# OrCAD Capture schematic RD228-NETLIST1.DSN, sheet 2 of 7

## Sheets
2 6: size A3
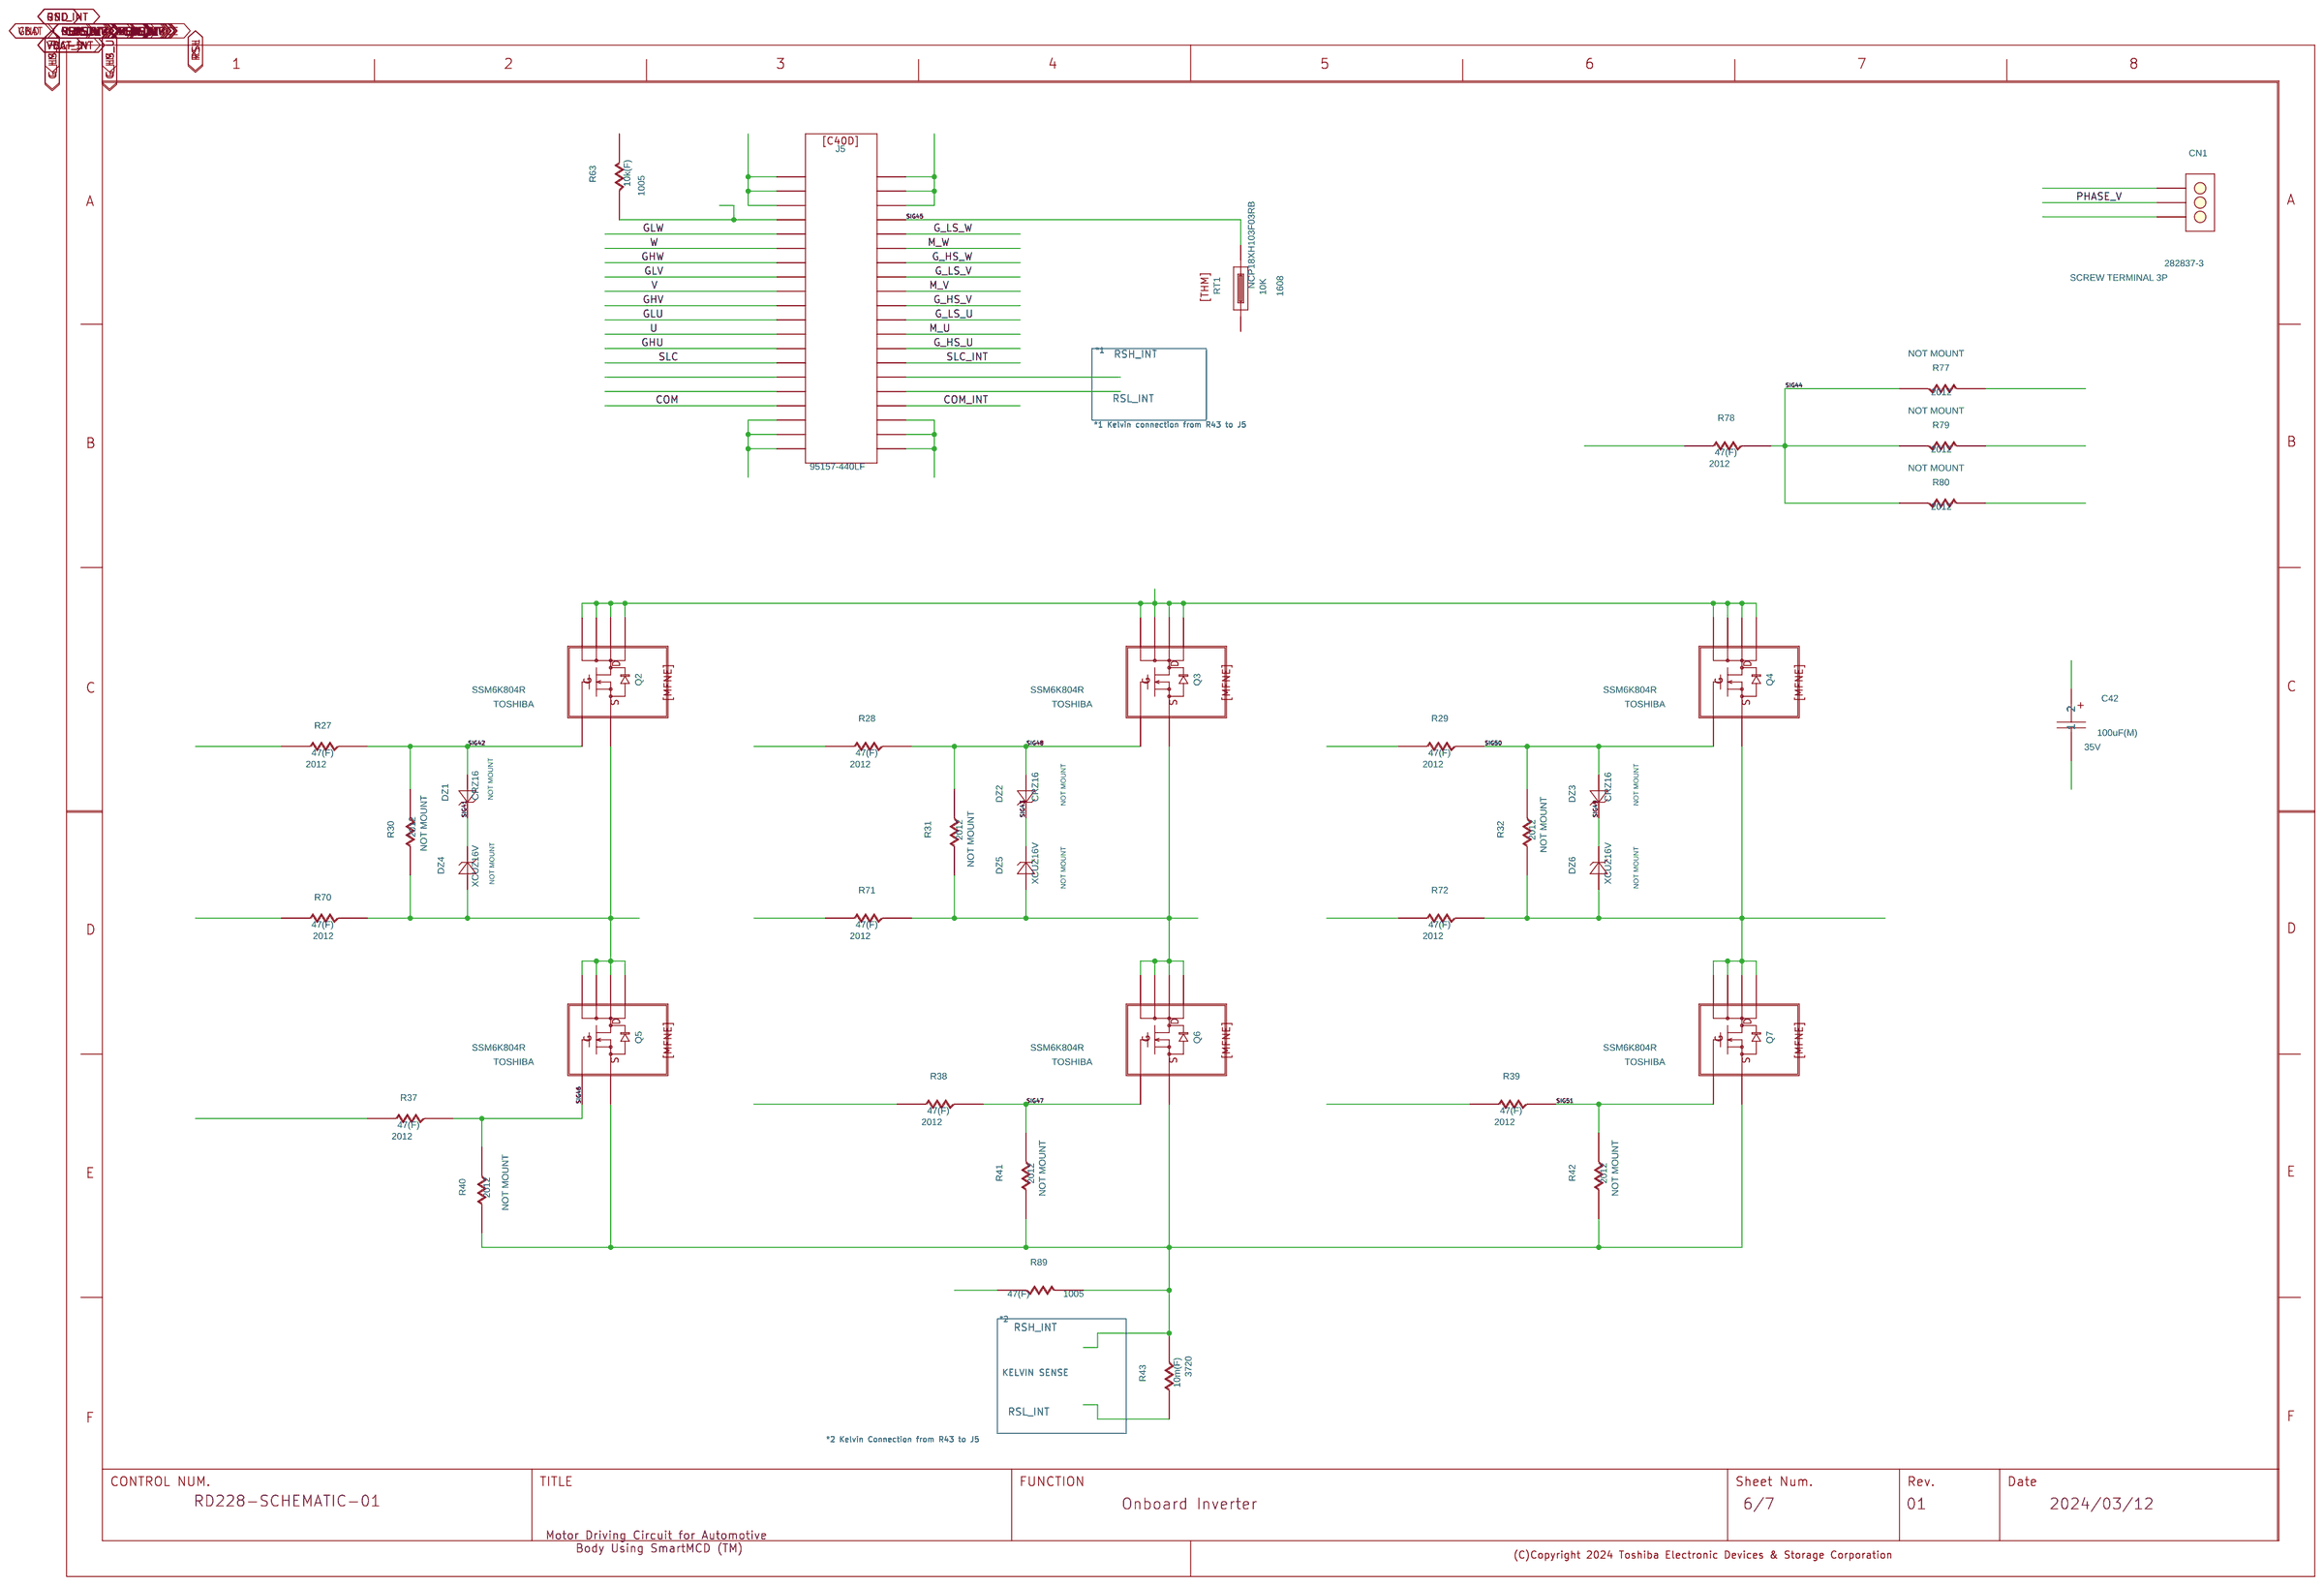
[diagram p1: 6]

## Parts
C42  100ƒÊF  [CAPAE660X550D700DD185L260N]
CN1  SCREW TERMINAL 3P  [SCREW_TERMINAL_3P_5_08]
DZ1  CRZ16  [SFLAT300P360X150X100-2N]
DZ2  CRZ16  [SFLAT300P360X150X100-2N]
DZ3  CRZ16  [SFLAT300P360X150X100-2N]
DZ4  NA  [XCUZ230P125X250X100-2N]
DZ5  NA  [XCUZ230P125X250X100-2N]
DZ6  NA  [XCUZ230P125X250X100-2N]
J5  HM 2x20  [HM254P2x20-SMD]
Q2  NA  [TSOP6F95P220X290X80-6N]
Q3  NA  [TSOP6F95P220X290X80-6N]
Q4  NA  [TSOP6F95P220X290X80-6N]
Q5  NA  [TSOP6F95P220X290X80-6N]
Q6  NA  [TSOP6F95P220X290X80-6N]
Q7  NA  [TSOP6F95P220X290X80-6N]
R27  47  [RESC2013X38N-0805-NOOVERLAY]
R28  47  [RESC2013X38N-0805-NOOVERLAY]
R29  47  [RESC2013X38N-0805-NOOVERLAY]
R30  9.1k  [RESC2013X38N-0805-NOOVERLAY]
R31  9.1k  [RESC2013X38N-0805-NOOVERLAY]
R32  9.1k  [RESC2013X38N-0805-NOOVERLAY]
R37  47  [RESC2013X38N-0805-NOOVERLAY]
R38  47  [RESC2013X38N-0805-NOOVERLAY]
R39  47  [RESC2013X38N-0805-NOOVERLAY]
R40  9.1k  [RESC2013X38N-0805-NOOVERLAY]
R41  9.1k  [RESC2013X38N-0805-NOOVERLAY]
R42  9.1k  [RESC2013X38N-0805-NOOVERLAY]
R43  0.01  [RES1508wide]
R63  10k  [RESC1005X40N-0402-NOOVERLAY]
R70  47  [RESC2013X38N-0805-NOOVERLAY]
R71  47  [RESC2013X38N-0805-NOOVERLAY]
R72  47  [RESC2013X38N-0805-NOOVERLAY]
R77  10k  [RESC2013X38N-0805-NOOVERLAY]
R78  47  [RESC2013X38N-0805-NOOVERLAY]
R79  10k  [RESC2013X38N-0805-NOOVERLAY]
R80  10k  [RESC2013X38N-0805-NOOVERLAY]
R89  47  [RESC1005X40N-0402-NOOVERLAY]
RT1  NA  [RESC1508X55N-0603-NOOVERLAY]
U?#1  WAKU_DEF100

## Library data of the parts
C42 = CP: ASSEMBLY: SMD; BARCODE: 3500000142313; CATEGORY: Capacitors; COMP: Capacitor_Electrolytic_C42; COMPONENTNAME: Capacitor_Electrolytic_C42_Capacitor_Electrolytic_C42; COMPONENTTYPE: 4; DATASHEET URL: http://nichicon-us.com/english/products/pdfs/e-uwt.pdf; FAMILY: ALUMINUM CAPACITOR; ID: 395; INSTANCENAME: INS5635; ITEM_ID: 12367; LAYOUTNAME: Z-29bafe88-5e4d-49ea-814c-92cf843dcf65.cmp15; MANUFACTURER: Nichicon; MANUFACTURER PART NUMBER: UWT1V101MCL1GS; NUMBER DEVICES IN PACKAGE: 1; PACKAGE CASE: Radial, Can - SMD; PART TYPE: Capacitors; PIN NAMES ROTATE: True; PIN NAMES VISIBLE: False; PIN NUMBERS VISIBLE: False; TOLERANCE: }20%; VAL1: 100uF(M); VAL2: 35V; VAL3: UWT1V101MCL1GS; VOLTAGE RATING: 35V
CN1 = SCREW_TERMINAL_3P: ASSEMBLY: TH; BARCODE: 3500000283597; CATEGORY: Connectors, Interconnects; COMP: SCREW_TERMINAL_3P_CN1; COMPONENTNAME: SCREW_TERMINAL_3P_CN1_SCREW_TERMINAL_3P_CN1; COMPONENTTYPE: 4; DATASHEET URL: https://www.te.com/commerce/DocumentDelivery/DDEController?Action; FAMILY: TERMINAL BLOCK; FEATURES: Interlocking (Side); ID: 1109; INSTANCENAME: INS5817; ITEM_ID: 25504; LAYOUTNAME: Z-29bafe88-5e4d-49ea-814c-92cf843dcf65.cmp142; MANUFACTURER: TE Connectivity AMP Connectors; MANUFACTURER PART NUMBER: 282837-3; MOUNTING TYPE: Through Hole; NUMBER DEVICES IN PACKAGE: 1; NUMBER OF LEVELS: 1; NUMBER OF PINS: 3; PART TYPE: Connectors, Electromechanical; PIN NAMES ROTATE: True; PIN NAMES VISIBLE: False; PIN NUMBERS VISIBLE: False; PITCH: 0.200" (5.08mm); POSITIONS PER LEVEL: 3; VAL3: 282837-3
DZ1 = DIODE_ZENER: ASSEMBLY: SMD; BARCODE: 3500000349811; CATEGORY: Diodes - Zener - Single; COMP: Diode_Zener_DZ1; COMPONENTNAME: Diode_Zener_DZ1_Diode_Zener_DZ1; COMPONENTTYPE: 4; DATASHEET URL: https://toshiba.semicon-storage.com/info/docget.jsp?did; FAMILY: DIODE ZENER; ID: 921; INSTANCENAME: INS5575; ITEM_ID: 32142; LAYOUTNAME: Z-29bafe88-5e4d-49ea-814c-92cf843dcf65.cmp37; MANUFACTURER: Toshiba Semiconductor and Storage; MANUFACTURER PART NUMBER: CRZ16(TE85L,Q,M); NOTMOUNT: NOT MOUNT; NUMBER DEVICES IN PACKAGE: 1; PACKAGE CASE: SOD-123F; PART TYPE: Discrete Semiconductors; PIN NAMES ROTATE: True; PIN NAMES VISIBLE: False; PIN NUMBERS VISIBLE: False; POWER MAX: 700 mW; TOLERANCE: }10%; UPDATEDATE: 2024/2/26; UPDATETIME: 11:30:07; UPDATEUSER: w20165dm; VOLTAGE  FORWARD: 1 V @ 200 mA; VOLTAGE  ZENER: 16 V
DZ2 = DIODE_ZENER: ASSEMBLY: SMD; BARCODE: 3500000349811; CATEGORY: Diodes - Zener - Single; COMP: Diode_Zener_DZ2; COMPONENTNAME: Diode_Zener_DZ2_Diode_Zener_DZ2; COMPONENTTYPE: 4; DATASHEET URL: https://toshiba.semicon-storage.com/info/docget.jsp?did; FAMILY: DIODE ZENER; ID: 921; INSTANCENAME: INS5565; ITEM_ID: 32142; LAYOUTNAME: Z-29bafe88-5e4d-49ea-814c-92cf843dcf65.cmp6; MANUFACTURER: Toshiba Semiconductor and Storage; MANUFACTURER PART NUMBER: CRZ16(TE85L,Q,M); NOTMOUNT: NOT MOUNT; NUMBER DEVICES IN PACKAGE: 1; PACKAGE CASE: SOD-123F; PART TYPE: Discrete Semiconductors; PIN NAMES ROTATE: True; PIN NAMES VISIBLE: False; PIN NUMBERS VISIBLE: False; POWER MAX: 700 mW; TOLERANCE: }10%; UPDATEDATE: 2024/2/26; UPDATETIME: 11:30:07; UPDATEUSER: w20165dm; VOLTAGE  FORWARD: 1 V @ 200 mA; VOLTAGE  ZENER: 16 V
DZ3 = DIODE_ZENER: ASSEMBLY: SMD; BARCODE: 3500000349811; CATEGORY: Diodes - Zener - Single; COMP: Diode_Zener_DZ2; COMPONENTNAME: Diode_Zener_DZ2_Diode_Zener_DZ2; COMPONENTTYPE: 4; DATASHEET URL: https://toshiba.semicon-storage.com/info/docget.jsp?did; FAMILY: DIODE ZENER; ID: 921; INSTANCENAME: INS5565; ITEM_ID: 32142; LAYOUTNAME: Z-29bafe88-5e4d-49ea-814c-92cf843dcf65.cmp129; MANUFACTURER: Toshiba Semiconductor and Storage; MANUFACTURER PART NUMBER: CRZ16(TE85L,Q,M); NOTMOUNT: NOT MOUNT; NUMBER DEVICES IN PACKAGE: 1; PACKAGE CASE: SOD-123F; PART TYPE: Discrete Semiconductors; PIN NAMES ROTATE: True; PIN NAMES VISIBLE: False; PIN NUMBERS VISIBLE: False; POWER MAX: 700 mW; TOLERANCE: }10%; UPDATEDATE: 2024/2/26; UPDATETIME: 11:30:07; UPDATEUSER: w20165dm; VOLTAGE  FORWARD: 1 V @ 200 mA; VOLTAGE  ZENER: 16 V
DZ4 = DIODE_ZENER: ASSEMBLY: SMD; BARCODE: 3500000349828; CATEGORY: Diodes - Zener - Single; COMP: Diode_Zener_DZ4; COMPONENTNAME: Diode_Zener_DZ4_Diode_Zener_DZ4; COMPONENTTYPE: 4; FAMILY: DIODE ZENER; ID: 922; INSTANCENAME: INS5605; ITEM_ID: 32143; LAYOUTNAME: Z-29bafe88-5e4d-49ea-814c-92cf843dcf65.cmp13; MANUFACTURER: Toshiba Semiconductor and Storage; MANUFACTURER PART NUMBER: XCUZ16V; NOTMOUNT: NOT MOUNT; NUMBER DEVICES IN PACKAGE: 1; PACKAGE CASE: SOD-123F; PART TYPE: Discrete Semiconductors; PIN NAMES ROTATE: True; PIN NAMES VISIBLE: False; PIN NUMBERS VISIBLE: False; UPDATEDATE: 2024/2/26; UPDATETIME: 11:30:07; UPDATEUSER: w20165dm; VAL1: XCUZ16V; VAL3: XCUZ16V; VOLTAGE  ZENER: 16 V
DZ5 = DIODE_ZENER: ASSEMBLY: SMD; BARCODE: 3500000349828; CATEGORY: Diodes - Zener - Single; COMP: Diode_Zener_DZ5; COMPONENTNAME: Diode_Zener_DZ5_Diode_Zener_DZ5; COMPONENTTYPE: 4; FAMILY: DIODE ZENER; ID: 922; INSTANCENAME: INS5595; ITEM_ID: 32143; LAYOUTNAME: Z-29bafe88-5e4d-49ea-814c-92cf843dcf65.cmp20; MANUFACTURER: Toshiba Semiconductor and Storage; MANUFACTURER PART NUMBER: XCUZ16V; NOTMOUNT: NOT MOUNT; NUMBER DEVICES IN PACKAGE: 1; PACKAGE CASE: SOD-123F; PART TYPE: Discrete Semiconductors; PIN NAMES ROTATE: True; PIN NAMES VISIBLE: False; PIN NUMBERS VISIBLE: False; UPDATEDATE: 2024/2/26; UPDATETIME: 11:30:07; UPDATEUSER: w20165dm; VAL1: XCUZ16V; VAL3: XCUZ16V; VOLTAGE  ZENER: 16 V
DZ6 = DIODE_ZENER: ASSEMBLY: SMD; BARCODE: 3500000349828; CATEGORY: Diodes - Zener - Single; COMP: Diode_Zener_DZ5; COMPONENTNAME: Diode_Zener_DZ5_Diode_Zener_DZ5; COMPONENTTYPE: 4; FAMILY: DIODE ZENER; ID: 922; INSTANCENAME: INS5595; ITEM_ID: 32143; LAYOUTNAME: Z-29bafe88-5e4d-49ea-814c-92cf843dcf65.cmp137; MANUFACTURER: Toshiba Semiconductor and Storage; MANUFACTURER PART NUMBER: XCUZ16V; NOTMOUNT: NOT MOUNT; NUMBER DEVICES IN PACKAGE: 1; PACKAGE CASE: SOD-123F; PART TYPE: Discrete Semiconductors; PIN NAMES ROTATE: True; PIN NAMES VISIBLE: False; PIN NUMBERS VISIBLE: False; UPDATEDATE: 2024/2/26; UPDATETIME: 11:30:07; UPDATEUSER: w20165dm; VAL1: XCUZ16V; VAL3: XCUZ16V; VOLTAGE  ZENER: 16 V
J5 = C40D: ASSEMBLY: SMD; BARCODE: 3500000135131; CATEGORY: Connectors, Interconnects; COMP: HM_2x20_J5; COMPONENTNAME: HM_2x20_J5_HM_2x20_J5; COMPONENTTYPE: 4; CONNECTOR TYPE: Header, Unshrouded; CONTACT FINISH: Tin; CONTACT TYPE: Male Pin; DATASHEET URL: http://portal.fciconnect.com/Comergent//fci/drawing/95157.pdf; FAMILY: HEADER MALE; ID: 329; INSTANCENAME: INS5943; ITEM_ID: 11646; LAYOUTNAME: Z-29bafe88-5e4d-49ea-814c-92cf843dcf65.cmp36; MANUFACTURER: Amphenol FCI; MANUFACTURER PART NUMBER: 95157-440LF; MOUNTING TYPE: Surface Mount; NUMBER DEVICES IN PACKAGE: 1; NUMBER OF POSITIONS: 40; NUMBER OF ROWS: 2; PART TYPE: Connectors, Electromechanical; PIN NAMES ROTATE: True; PIN NAMES VISIBLE: False; PIN NUMBERS VISIBLE: True; PITCH: 0.100" (2.54mm); TERMINATION: Solder; VAL3: 95157-440LF
Q2 = MFNE: ASSEMBLY: SMD; AUTHOR: t5459927; BARCODE: 3500000348838; CATEGORY: Transistors - FETs, MOSFETs - Single; COMP: SSM6K804R_Q5; COMPONENTNAME: SSM6K804R_Q5_SSM6K804R_Q5; COMPONENTTYPE: 4; CURRENT  CONTINUOUS DRAIN: 12A; DATE: 2024/2/16; DRAIN TO SOURCE VOLTAGE: 40V; FAMILY: FET; FET TYPE: N-Channel; ID: 916; INSTANCENAME: INS4477; ITEM_ID: 32044; LAYOUTNAME: Z-29bafe88-5e4d-49ea-814c-92cf843dcf65.cmp121; MANUFACTURER: Toshiba Semiconductor and Storage; MANUFACTURER PART NUMBER: SSM6K804R; NUMBER DEVICES IN PACKAGE: 1; PACKAGE CASE: TSOP6F; PART TYPE: Discrete Semiconductors; PIN NAMES ROTATE: True; PIN NAMES VISIBLE: False; PIN NUMBERS VISIBLE: True; RDS ON MAX: 12mOhm @ 4A, 4.5V; TIME: 16:56:46; UPDATEDATE: 2024/2/16; UPDATETIME: 16:56:46; UPDATEUSER: t5459927; USERCOMPTEXT3: TOSHIBA; VAL1: SSM6K804R; VAL3: SSM6K804R; VGS: -20/+20
Q3 = MFNE: ASSEMBLY: SMD; AUTHOR: t5459927; BARCODE: 3500000348838; CATEGORY: Transistors - FETs, MOSFETs - Single; COMP: SSM6K804R_Q5; COMPONENTNAME: SSM6K804R_Q5_SSM6K804R_Q5; COMPONENTTYPE: 4; CURRENT  CONTINUOUS DRAIN: 12A; DATE: 2024/2/16; DRAIN TO SOURCE VOLTAGE: 40V; FAMILY: FET; FET TYPE: N-Channel; ID: 916; INSTANCENAME: INS4477; ITEM_ID: 32044; LAYOUTNAME: Z-29bafe88-5e4d-49ea-814c-92cf843dcf65.cmp124; MANUFACTURER: Toshiba Semiconductor and Storage; MANUFACTURER PART NUMBER: SSM6K804R; NUMBER DEVICES IN PACKAGE: 1; PACKAGE CASE: TSOP6F; PART TYPE: Discrete Semiconductors; PIN NAMES ROTATE: True; PIN NAMES VISIBLE: False; PIN NUMBERS VISIBLE: True; RDS ON MAX: 12mOhm @ 4A, 4.5V; TIME: 16:56:46; UPDATEDATE: 2024/2/16; UPDATETIME: 16:56:46; UPDATEUSER: t5459927; USERCOMPTEXT3: TOSHIBA; VAL1: SSM6K804R; VAL3: SSM6K804R; VGS: -20/+20
Q4 = MFNE: ASSEMBLY: SMD; AUTHOR: t5459927; BARCODE: 3500000348838; CATEGORY: Transistors - FETs, MOSFETs - Single; COMP: SSM6K804R_Q5; COMPONENTNAME: SSM6K804R_Q5_SSM6K804R_Q5; COMPONENTTYPE: 4; CURRENT  CONTINUOUS DRAIN: 12A; DATE: 2024/2/16; DRAIN TO SOURCE VOLTAGE: 40V; FAMILY: FET; FET TYPE: N-Channel; ID: 916; INSTANCENAME: INS4477; ITEM_ID: 32044; LAYOUTNAME: Z-29bafe88-5e4d-49ea-814c-92cf843dcf65.cmp126; MANUFACTURER: Toshiba Semiconductor and Storage; MANUFACTURER PART NUMBER: SSM6K804R; NUMBER DEVICES IN PACKAGE: 1; PACKAGE CASE: TSOP6F; PART TYPE: Discrete Semiconductors; PIN NAMES ROTATE: True; PIN NAMES VISIBLE: False; PIN NUMBERS VISIBLE: True; RDS ON MAX: 12mOhm @ 4A, 4.5V; TIME: 16:56:46; UPDATEDATE: 2024/2/16; UPDATETIME: 16:56:46; UPDATEUSER: t5459927; USERCOMPTEXT3: TOSHIBA; VAL1: SSM6K804R; VAL3: SSM6K804R; VGS: -20/+20
Q5 = MFNE: ASSEMBLY: SMD; AUTHOR: t5459927; BARCODE: 3500000348838; CATEGORY: Transistors - FETs, MOSFETs - Single; COMP: SSM6K804R_Q5; COMPONENTNAME: SSM6K804R_Q5_SSM6K804R_Q5; COMPONENTTYPE: 4; CURRENT  CONTINUOUS DRAIN: 12A; DATE: 2024/2/16; DRAIN TO SOURCE VOLTAGE: 40V; FAMILY: FET; FET TYPE: N-Channel; ID: 916; INSTANCENAME: INS4477; ITEM_ID: 32044; LAYOUTNAME: Z-29bafe88-5e4d-49ea-814c-92cf843dcf65.cmp120; MANUFACTURER: Toshiba Semiconductor and Storage; MANUFACTURER PART NUMBER: SSM6K804R; NUMBER DEVICES IN PACKAGE: 1; PACKAGE CASE: TSOP6F; PART TYPE: Discrete Semiconductors; PIN NAMES ROTATE: True; PIN NAMES VISIBLE: False; PIN NUMBERS VISIBLE: True; RDS ON MAX: 12mOhm @ 4A, 4.5V; TIME: 16:56:46; UPDATEDATE: 2024/2/16; UPDATETIME: 16:56:46; UPDATEUSER: t5459927; USERCOMPTEXT3: TOSHIBA; VAL1: SSM6K804R; VAL3: SSM6K804R; VGS: -20/+20
Q6 = MFNE: ASSEMBLY: SMD; AUTHOR: t5459927; BARCODE: 3500000348838; CATEGORY: Transistors - FETs, MOSFETs - Single; COMP: SSM6K804R_Q5; COMPONENTNAME: SSM6K804R_Q5_SSM6K804R_Q5; COMPONENTTYPE: 4; CURRENT  CONTINUOUS DRAIN: 12A; DATE: 2024/2/16; DRAIN TO SOURCE VOLTAGE: 40V; FAMILY: FET; FET TYPE: N-Channel; ID: 916; INSTANCENAME: INS4477; ITEM_ID: 32044; LAYOUTNAME: Z-29bafe88-5e4d-49ea-814c-92cf843dcf65.cmp125; MANUFACTURER: Toshiba Semiconductor and Storage; MANUFACTURER PART NUMBER: SSM6K804R; NUMBER DEVICES IN PACKAGE: 1; PACKAGE CASE: TSOP6F; PART TYPE: Discrete Semiconductors; PIN NAMES ROTATE: True; PIN NAMES VISIBLE: False; PIN NUMBERS VISIBLE: True; RDS ON MAX: 12mOhm @ 4A, 4.5V; TIME: 16:56:46; UPDATEDATE: 2024/2/16; UPDATETIME: 16:56:46; UPDATEUSER: t5459927; USERCOMPTEXT3: TOSHIBA; VAL1: SSM6K804R; VAL3: SSM6K804R; VGS: -20/+20
Q7 = MFNE: ASSEMBLY: SMD; AUTHOR: t5459927; BARCODE: 3500000348838; CATEGORY: Transistors - FETs, MOSFETs - Single; COMP: SSM6K804R_Q5; COMPONENTNAME: SSM6K804R_Q5_SSM6K804R_Q5; COMPONENTTYPE: 4; CURRENT  CONTINUOUS DRAIN: 12A; DATE: 2024/2/16; DRAIN TO SOURCE VOLTAGE: 40V; FAMILY: FET; FET TYPE: N-Channel; ID: 916; INSTANCENAME: INS4477; ITEM_ID: 32044; LAYOUTNAME: Z-29bafe88-5e4d-49ea-814c-92cf843dcf65.cmp133; MANUFACTURER: Toshiba Semiconductor and Storage; MANUFACTURER PART NUMBER: SSM6K804R; NUMBER DEVICES IN PACKAGE: 1; PACKAGE CASE: TSOP6F; PART TYPE: Discrete Semiconductors; PIN NAMES ROTATE: True; PIN NAMES VISIBLE: False; PIN NUMBERS VISIBLE: True; RDS ON MAX: 12mOhm @ 4A, 4.5V; TIME: 16:56:46; UPDATEDATE: 2024/2/16; UPDATETIME: 16:56:46; UPDATEUSER: t5459927; USERCOMPTEXT3: TOSHIBA; VAL1: SSM6K804R; VAL3: SSM6K804R; VGS: -20/+20
R27 = R: ASSEMBLY: SMD; AUTHOR: t5459927; BARCODE: 0100000003824; CATEGORY: Resistors; COMP: Resistor_R27; COMPONENTNAME: Resistor_R27_Resistor_R27; COMPONENTTYPE: 4; DATASHEET URL: http://www.yageo.com/NewPortal/yageodocoutput?fileName; DATE: 2024/2/16; FAMILY: RESISTOR; ID: 124; INSTANCENAME: INS5421; ITEM_ID: 648; LAYOUTNAME: Z-29bafe88-5e4d-49ea-814c-92cf843dcf65.cmp23; MANUFACTURER: Yageo; MANUFACTURER PART NUMBER: RC0805FR-0747RL; NUMBER DEVICES IN PACKAGE: 1; PACKAGE CASE: 0805 (2012 Metric); PART TYPE: Resistors; PIN NAMES ROTATE: True; PIN NAMES VISIBLE: False; PIN NUMBERS VISIBLE: False; POWER: 0.125W, 1/8W; SAVECOUNT: 0; SIZECODESMD: 2012; TEMPERATURE COEFFICIENT: }100ppm/C; TIME: 16:56:58; TOLERANCE: }1%; UPDATEDATE: 2024/2/16; UPDATETIME: 16:56:58; UPDATEUSER: t5459927; VAL1: 47(F); VAL2: 0.125W; VAL3: RC0805FR-0747RL
R28 = R: ASSEMBLY: SMD; AUTHOR: t5459927; BARCODE: 0100000003824; CATEGORY: Resistors; COMP: Resistor_R28; COMPONENTNAME: Resistor_R28_Resistor_R28; COMPONENTTYPE: 4; DATASHEET URL: http://www.yageo.com/NewPortal/yageodocoutput?fileName; DATE: 2024/2/16; FAMILY: RESISTOR; ID: 124; INSTANCENAME: INS5391; ITEM_ID: 648; LAYOUTNAME: Z-29bafe88-5e4d-49ea-814c-92cf843dcf65.cmp21; MANUFACTURER: Yageo; MANUFACTURER PART NUMBER: RC0805FR-0747RL; NUMBER DEVICES IN PACKAGE: 1; PACKAGE CASE: 0805 (2012 Metric); PART TYPE: Resistors; PIN NAMES ROTATE: True; PIN NAMES VISIBLE: False; PIN NUMBERS VISIBLE: False; POWER: 0.125W, 1/8W; SAVECOUNT: 0; SIZECODESMD: 2012; TEMPERATURE COEFFICIENT: }100ppm/C; TIME: 16:56:40; TOLERANCE: }1%; UPDATEDATE: 2024/2/16; UPDATETIME: 16:56:40; UPDATEUSER: t5459927; VAL1: 47(F); VAL2: 0.125W; VAL3: RC0805FR-0747RL
R29 = R: ASSEMBLY: SMD; AUTHOR: t5459927; BARCODE: 0100000003824; CATEGORY: Resistors; COMP: Resistor_R28; COMPONENTNAME: Resistor_R28_Resistor_R28; COMPONENTTYPE: 4; DATASHEET URL: http://www.yageo.com/NewPortal/yageodocoutput?fileName; DATE: 2024/2/16; FAMILY: RESISTOR; ID: 124; INSTANCENAME: INS5391; ITEM_ID: 648; LAYOUTNAME: Z-29bafe88-5e4d-49ea-814c-92cf843dcf65.cmp132; MANUFACTURER: Yageo; MANUFACTURER PART NUMBER: RC0805FR-0747RL; NUMBER DEVICES IN PACKAGE: 1; PACKAGE CASE: 0805 (2012 Metric); PART TYPE: Resistors; PIN NAMES ROTATE: True; PIN NAMES VISIBLE: False; PIN NUMBERS VISIBLE: False; POWER: 0.125W, 1/8W; SAVECOUNT: 0; SIZECODESMD: 2012; TEMPERATURE COEFFICIENT: }100ppm/C; TIME: 16:56:40; TOLERANCE: }1%; UPDATEDATE: 2024/2/16; UPDATETIME: 16:56:40; UPDATEUSER: t5459927; VAL1: 47(F); VAL2: 0.125W; VAL3: RC0805FR-0747RL
R30 = R: ASSEMBLY: SMD; AUTHOR: t5459927; CATEGORY: Resistors; COMP: Resistor_R30; COMPONENTNAME: Resistor_R30_Resistor_R30; COMPONENTTYPE: 4; DATE: 2024/2/16; FAMILY: RESISTOR; ID: 124; INSTANCENAME: INS5411; ITEM_ID: 648; LAYOUTNAME: Z-29bafe88-5e4d-49ea-814c-92cf843dcf65.cmp29; MANUFACTURER: Yageo; NOTMOUNT: NOT MOUNT; NUMBER DEVICES IN PACKAGE: 1; PACKAGE CASE: 0805 (2012 Metric); PART TYPE: Resistors; PIN NAMES ROTATE: True; PIN NAMES VISIBLE: False; PIN NUMBERS VISIBLE: False; POWER: 0.125W, 1/8W; SAVECOUNT: 0; SIZECODESMD: 2012; TEMPERATURE COEFFICIENT: }100ppm/C; TIME: 16:56:45; TOLERANCE: }1%; UPDATEDATE: 2024/2/16; UPDATETIME: 16:56:45; UPDATEUSER: t5459927
R31 = R: ASSEMBLY: SMD; AUTHOR: t5459927; CATEGORY: Resistors; COMP: Resistor_R31; COMPONENTNAME: Resistor_R31_Resistor_R31; COMPONENTTYPE: 4; DATE: 2024/2/16; FAMILY: RESISTOR; ID: 124; INSTANCENAME: INS5381; ITEM_ID: 648; LAYOUTNAME: Z-29bafe88-5e4d-49ea-814c-92cf843dcf65.cmp27; MANUFACTURER: Yageo; NOTMOUNT: NOT MOUNT; NUMBER DEVICES IN PACKAGE: 1; PACKAGE CASE: 0805 (2012 Metric); PART TYPE: Resistors; PIN NAMES ROTATE: True; PIN NAMES VISIBLE: False; PIN NUMBERS VISIBLE: False; POWER: 0.125W, 1/8W; SAVECOUNT: 0; SIZECODESMD: 2012; TEMPERATURE COEFFICIENT: }100ppm/C; TIME: 16:56:50; TOLERANCE: }1%; UPDATEDATE: 2024/2/16; UPDATETIME: 16:56:50; UPDATEUSER: t5459927
R32 = R: ASSEMBLY: SMD; AUTHOR: t5459927; CATEGORY: Resistors; COMP: Resistor_R31; COMPONENTNAME: Resistor_R31_Resistor_R31; COMPONENTTYPE: 4; DATE: 2024/2/16; FAMILY: RESISTOR; ID: 124; INSTANCENAME: INS5381; ITEM_ID: 648; LAYOUTNAME: Z-29bafe88-5e4d-49ea-814c-92cf843dcf65.cmp128; MANUFACTURER: Yageo; NOTMOUNT: NOT MOUNT; NUMBER DEVICES IN PACKAGE: 1; PACKAGE CASE: 0805 (2012 Metric); PART TYPE: Resistors; PIN NAMES ROTATE: True; PIN NAMES VISIBLE: False; PIN NUMBERS VISIBLE: False; POWER: 0.125W, 1/8W; SAVECOUNT: 0; SIZECODESMD: 2012; TEMPERATURE COEFFICIENT: }100ppm/C; TIME: 16:56:50; TOLERANCE: }1%; UPDATEDATE: 2024/2/16; UPDATETIME: 16:56:50; UPDATEUSER: t5459927
R37 = R: ASSEMBLY: SMD; AUTHOR: t5459927; BARCODE: 0100000003824; CATEGORY: Resistors; COMP: Resistor_R37; COMPONENTNAME: Resistor_R37_Resistor_R37; COMPONENTTYPE: 4; DATASHEET URL: http://www.yageo.com/NewPortal/yageodocoutput?fileName; DATE: 2024/2/16; FAMILY: RESISTOR; ID: 124; INSTANCENAME: INS5341; ITEM_ID: 648; LAYOUTNAME: Z-29bafe88-5e4d-49ea-814c-92cf843dcf65.cmp24; MANUFACTURER: Yageo; MANUFACTURER PART NUMBER: RC0805FR-0747RL; NUMBER DEVICES IN PACKAGE: 1; PACKAGE CASE: 0805 (2012 Metric); PART TYPE: Resistors; PIN NAMES ROTATE: True; PIN NAMES VISIBLE: False; PIN NUMBERS VISIBLE: False; POWER: 0.125W, 1/8W; SAVECOUNT: 0; SIZECODESMD: 2012; TEMPERATURE COEFFICIENT: }100ppm/C; TIME: 16:56:42; TOLERANCE: }1%; UPDATEDATE: 2024/2/16; UPDATETIME: 16:56:42; UPDATEUSER: t5459927; VAL1: 47(F); VAL2: 0.125W; VAL3: RC0805FR-0747RL
R38 = R: ASSEMBLY: SMD; AUTHOR: t5459927; BARCODE: 0100000003824; CATEGORY: Resistors; COMP: Resistor_R38; COMPONENTNAME: Resistor_R38_Resistor_R38; COMPONENTTYPE: 4; DATASHEET URL: http://www.yageo.com/NewPortal/yageodocoutput?fileName; DATE: 2024/2/16; FAMILY: RESISTOR; ID: 124; INSTANCENAME: INS5321; ITEM_ID: 648; LAYOUTNAME: Z-29bafe88-5e4d-49ea-814c-92cf843dcf65.cmp11; MANUFACTURER: Yageo; MANUFACTURER PART NUMBER: RC0805FR-0747RL; NUMBER DEVICES IN PACKAGE: 1; PACKAGE CASE: 0805 (2012 Metric); PART TYPE: Resistors; PIN NAMES ROTATE: True; PIN NAMES VISIBLE: False; PIN NUMBERS VISIBLE: False; POWER: 0.125W, 1/8W; SAVECOUNT: 0; SIZECODESMD: 2012; TEMPERATURE COEFFICIENT: }100ppm/C; TIME: 16:56:37; TOLERANCE: }1%; UPDATEDATE: 2024/2/16; UPDATETIME: 16:56:37; UPDATEUSER: t5459927; VAL1: 47(F); VAL2: 0.125W; VAL3: RC0805FR-0747RL
R39 = R: ASSEMBLY: SMD; AUTHOR: t5459927; BARCODE: 0100000003824; CATEGORY: Resistors; COMP: Resistor_R38; COMPONENTNAME: Resistor_R38_Resistor_R38; COMPONENTTYPE: 4; DATASHEET URL: http://www.yageo.com/NewPortal/yageodocoutput?fileName; DATE: 2024/2/16; FAMILY: RESISTOR; ID: 124; INSTANCENAME: INS5321; ITEM_ID: 648; LAYOUTNAME: Z-29bafe88-5e4d-49ea-814c-92cf843dcf65.cmp131; MANUFACTURER: Yageo; MANUFACTURER PART NUMBER: RC0805FR-0747RL; NUMBER DEVICES IN PACKAGE: 1; PACKAGE CASE: 0805 (2012 Metric); PART TYPE: Resistors; PIN NAMES ROTATE: True; PIN NAMES VISIBLE: False; PIN NUMBERS VISIBLE: False; POWER: 0.125W, 1/8W; SAVECOUNT: 0; SIZECODESMD: 2012; TEMPERATURE COEFFICIENT: }100ppm/C; TIME: 16:56:37; TOLERANCE: }1%; UPDATEDATE: 2024/2/16; UPDATETIME: 16:56:37; UPDATEUSER: t5459927; VAL1: 47(F); VAL2: 0.125W; VAL3: RC0805FR-0747RL
R40 = R: ASSEMBLY: SMD; AUTHOR: t5459927; CATEGORY: Resistors; COMP: Resistor_R40; COMPONENTNAME: Resistor_R40_Resistor_R40; COMPONENTTYPE: 4; DATE: 2024/2/16; FAMILY: RESISTOR; ID: 124; INSTANCENAME: INS5331; ITEM_ID: 648; LAYOUTNAME: Z-29bafe88-5e4d-49ea-814c-92cf843dcf65.cmp19; MANUFACTURER: Yageo; NOTMOUNT: NOT MOUNT; NUMBER DEVICES IN PACKAGE: 1; PACKAGE CASE: 0805 (2012 Metric); PART TYPE: Resistors; PIN NAMES ROTATE: True; PIN NAMES VISIBLE: False; PIN NUMBERS VISIBLE: False; POWER: 0.125W, 1/8W; SAVECOUNT: 0; SIZECODESMD: 2012; TEMPERATURE COEFFICIENT: }100ppm/C; TIME: 16:56:52; TOLERANCE: }1%; UPDATEDATE: 2024/2/16; UPDATETIME: 16:56:52; UPDATEUSER: t5459927
R41 = R: ASSEMBLY: SMD; AUTHOR: t5459927; CATEGORY: Resistors; COMP: Resistor_R41; COMPONENTNAME: Resistor_R41_Resistor_R41; COMPONENTTYPE: 4; DATE: 2024/2/16; FAMILY: RESISTOR; ID: 124; INSTANCENAME: INS5311; ITEM_ID: 648; LAYOUTNAME: Z-29bafe88-5e4d-49ea-814c-92cf843dcf65.cmp22; MANUFACTURER: Yageo; NOTMOUNT: NOT MOUNT; NUMBER DEVICES IN PACKAGE: 1; PACKAGE CASE: 0805 (2012 Metric); PART TYPE: Resistors; PIN NAMES ROTATE: True; PIN NAMES VISIBLE: False; PIN NUMBERS VISIBLE: False; POWER: 0.125W, 1/8W; SAVECOUNT: 0; SIZECODESMD: 2012; TEMPERATURE COEFFICIENT: }100ppm/C; TIME: 16:56:48; TOLERANCE: }1%; UPDATEDATE: 2024/2/16; UPDATETIME: 16:56:48; UPDATEUSER: t5459927
R42 = R: ASSEMBLY: SMD; AUTHOR: t5459927; CATEGORY: Resistors; COMP: Resistor_R41; COMPONENTNAME: Resistor_R41_Resistor_R41; COMPONENTTYPE: 4; DATE: 2024/2/16; FAMILY: RESISTOR; ID: 124; INSTANCENAME: INS5311; ITEM_ID: 648; LAYOUTNAME: Z-29bafe88-5e4d-49ea-814c-92cf843dcf65.cmp135; MANUFACTURER: Yageo; NOTMOUNT: NOT MOUNT; NUMBER DEVICES IN PACKAGE: 1; PACKAGE CASE: 0805 (2012 Metric); PART TYPE: Resistors; PIN NAMES ROTATE: True; PIN NAMES VISIBLE: False; PIN NUMBERS VISIBLE: False; POWER: 0.125W, 1/8W; SAVECOUNT: 0; SIZECODESMD: 2012; TEMPERATURE COEFFICIENT: }100ppm/C; TIME: 16:56:48; TOLERANCE: }1%; UPDATEDATE: 2024/2/16; UPDATETIME: 16:56:48; UPDATEUSER: t5459927
R43 = R: ASSEMBLY: SMD; AUTHOR: t5459927; BARCODE: 3500000169150; CATEGORY: Resistors; COMP: Resistor_R43; COMPONENTNAME: Resistor_R43_Resistor_R43; COMPONENTTYPE: 4; DATASHEET URL: http://www.susumu.co.jp/common/pdf/n_catalog_partition07_en.pdf; DATE: 2024/2/16; FAMILY: RESISTOR; ID: 892; INSTANCENAME: INS6213; ITEM_ID: 15050; LAYOUTNAME: Z-29bafe88-5e4d-49ea-814c-92cf843dcf65.cmp5; MANUFACTURER: Susumu; MANUFACTURER PART NUMBER: RL3720WT-R010-F; NUMBER DEVICES IN PACKAGE: 1; PACKAGE CASE: Wide 1508 (3720 Metric), 0815; PART TYPE: Resistors; PIN NAMES ROTATE: True; PIN NAMES VISIBLE: False; PIN NUMBERS VISIBLE: False; POWER: 1W; SAVECOUNT: 0; SIZECODESMD: 3720; TEMPERATURE COEFFICIENT: 0/ +350ppm/C; TIME: 16:56:49; TOLERANCE: }1%; UPDATEDATE: 2024/2/16; UPDATETIME: 16:56:49; UPDATEUSER: t5459927; VAL1: 10m(F); VAL2: 1W; VAL3: RL3720WT-R010-F
R63 = R: ASSEMBLY: SMD; AUTHOR: t5459927; BARCODE: 2911010036805; CATEGORY: Resistors; COMP: Resistor_R63; COMPONENTNAME: Resistor_R63_Resistor_R63; COMPONENTTYPE: 4; DATASHEET URL: http://www.yageo.com/NewPortal/yageodocoutput?fileName; DATE: 2024/2/16; FAMILY: RESISTOR; ID: 68; INSTANCENAME: INS5155; ITEM_ID: 4341; LAYOUTNAME: Z-29bafe88-5e4d-49ea-814c-92cf843dcf65.cmp31; MANUFACTURER: Yageo; MANUFACTURER PART NUMBER: RC0402FR-0710KL; NUMBER DEVICES IN PACKAGE: 1; PACKAGE CASE: 0402 (1005 Metric); PART TYPE: Resistors; PIN NAMES ROTATE: True; PIN NAMES VISIBLE: False; PIN NUMBERS VISIBLE: False; POWER: 0.063W, 1/16W; RECOMMENDED RATING: Platinum; SAVECOUNT: 0; SIZECODESMD: 1005; TEMPERATURE COEFFICIENT: }100ppm/C; TIME: 16:56:42; TOLERANCE: }1%; UPDATEDATE: 2024/2/16; UPDATETIME: 16:56:42; UPDATEUSER: t5459927; VAL1: 10k(F); VAL2: 63mW; VAL3: RC0402FR-0710KL
R70 = R: ASSEMBLY: SMD; AUTHOR: t5459927; BARCODE: 0100000003824; CATEGORY: Resistors; COMP: Resistor_R70; COMPONENTNAME: Resistor_R70_Resistor_R70; COMPONENTTYPE: 4; DATASHEET URL: http://www.yageo.com/NewPortal/yageodocoutput?fileName; DATE: 2024/2/16; FAMILY: RESISTOR; ID: 124; INSTANCENAME: INS5431; ITEM_ID: 648; LAYOUTNAME: Z-29bafe88-5e4d-49ea-814c-92cf843dcf65.cmp10; MANUFACTURER: Yageo; MANUFACTURER PART NUMBER: RC0805FR-0747RL; NUMBER DEVICES IN PACKAGE: 1; PACKAGE CASE: 0805 (2012 Metric); PART TYPE: Resistors; PIN NAMES ROTATE: True; PIN NAMES VISIBLE: False; PIN NUMBERS VISIBLE: False; POWER: 0.125W, 1/8W; SAVECOUNT: 0; SIZECODESMD: 2012; TEMPERATURE COEFFICIENT: }100ppm/C; TIME: 16:56:49; TOLERANCE: }1%; UPDATEDATE: 2024/2/16; UPDATETIME: 16:56:49; UPDATEUSER: t5459927; VAL1: 47(F); VAL2: 0.125W; VAL3: RC0805FR-0747RL
R71 = R: ASSEMBLY: SMD; AUTHOR: t5459927; BARCODE: 0100000003824; CATEGORY: Resistors; COMP: Resistor_R71; COMPONENTNAME: Resistor_R71_Resistor_R71; COMPONENTTYPE: 4; DATASHEET URL: http://www.yageo.com/NewPortal/yageodocoutput?fileName; DATE: 2024/2/16; FAMILY: RESISTOR; ID: 124; INSTANCENAME: INS5401; ITEM_ID: 648; LAYOUTNAME: Z-29bafe88-5e4d-49ea-814c-92cf843dcf65.cmp33; MANUFACTURER: Yageo; MANUFACTURER PART NUMBER: RC0805FR-0747RL; NUMBER DEVICES IN PACKAGE: 1; PACKAGE CASE: 0805 (2012 Metric); PART TYPE: Resistors; PIN NAMES ROTATE: True; PIN NAMES VISIBLE: False; PIN NUMBERS VISIBLE: False; POWER: 0.125W, 1/8W; SAVECOUNT: 0; SIZECODESMD: 2012; TEMPERATURE COEFFICIENT: }100ppm/C; TIME: 16:56:54; TOLERANCE: }1%; UPDATEDATE: 2024/2/16; UPDATETIME: 16:56:54; UPDATEUSER: t5459927; VAL1: 47(F); VAL2: 0.125W; VAL3: RC0805FR-0747RL
R72 = R: ASSEMBLY: SMD; AUTHOR: t5459927; BARCODE: 0100000003824; CATEGORY: Resistors; COMP: Resistor_R71; COMPONENTNAME: Resistor_R71_Resistor_R71; COMPONENTTYPE: 4; DATASHEET URL: http://www.yageo.com/NewPortal/yageodocoutput?fileName; DATE: 2024/2/16; FAMILY: RESISTOR; ID: 124; INSTANCENAME: INS5401; ITEM_ID: 648; LAYOUTNAME: Z-29bafe88-5e4d-49ea-814c-92cf843dcf65.cmp136; MANUFACTURER: Yageo; MANUFACTURER PART NUMBER: RC0805FR-0747RL; NUMBER DEVICES IN PACKAGE: 1; PACKAGE CASE: 0805 (2012 Metric); PART TYPE: Resistors; PIN NAMES ROTATE: True; PIN NAMES VISIBLE: False; PIN NUMBERS VISIBLE: False; POWER: 0.125W, 1/8W; SAVECOUNT: 0; SIZECODESMD: 2012; TEMPERATURE COEFFICIENT: }100ppm/C; TIME: 16:56:54; TOLERANCE: }1%; UPDATEDATE: 2024/2/16; UPDATETIME: 16:56:54; UPDATEUSER: t5459927; VAL1: 47(F); VAL2: 0.125W; VAL3: RC0805FR-0747RL
R77 = R: ASSEMBLY: SMD; AUTHOR: t5459927; BARCODE: 0100000001974; CATEGORY: Resistors; COMP: Resistor_R77; COMPONENTNAME: Resistor_R77_Resistor_R77; COMPONENTTYPE: 4; DATASHEET URL: http://www.yageo.com/NewPortal/yageodocoutput?fileName; DATE: 2024/2/16; FAMILY: RESISTOR; ID: 228; INSTANCENAME: INS6403; ITEM_ID: 462; MANUFACTURER: Yageo; MANUFACTURER PART NUMBER: RC0805FR-0710KL; NOTMOUNT: NOT MOUNT; NUMBER DEVICES IN PACKAGE: 1; PACKAGE CASE: 0805 (2012 Metric); PART TYPE: Resistors; PIN NAMES ROTATE: True; PIN NAMES VISIBLE: False; PIN NUMBERS VISIBLE: False; POWER: 0.125W, 1/8W; RECOMMENDED RATING: Platinum; SAVECOUNT: 0; SIZECODESMD: 2012; TEMPERATURE COEFFICIENT: }100ppm/C; TIME: 16:56:53; TOLERANCE: }1%; UPDATEDATE: 2024/2/16; UPDATETIME: 16:56:53; UPDATEUSER: t5459927
R78 = R: ASSEMBLY: SMD; AUTHOR: t5459927; BARCODE: 0100000003824; CATEGORY: Resistors; COMP: Resistor_R78; COMPONENTNAME: Resistor_R78_Resistor_R78; COMPONENTTYPE: 4; DATASHEET URL: http://www.yageo.com/NewPortal/yageodocoutput?fileName; DATE: 2024/2/16; FAMILY: RESISTOR; ID: 124; INSTANCENAME: INS5625; ITEM_ID: 648; LAYOUTNAME: Z-29bafe88-5e4d-49ea-814c-92cf843dcf65.cmp34; MANUFACTURER: Yageo; MANUFACTURER PART NUMBER: RC0805FR-0747RL; NUMBER DEVICES IN PACKAGE: 1; PACKAGE CASE: 0805 (2012 Metric); PART TYPE: Resistors; PIN NAMES ROTATE: True; PIN NAMES VISIBLE: False; PIN NUMBERS VISIBLE: False; POWER: 0.125W, 1/8W; SAVECOUNT: 0; SIZECODESMD: 2012; TEMPERATURE COEFFICIENT: }100ppm/C; TIME: 16:56:58; TOLERANCE: }1%; UPDATEDATE: 2024/2/16; UPDATETIME: 16:56:58; UPDATEUSER: t5459927; VAL1: 47(F); VAL2: 0.125W; VAL3: RC0805FR-0747RL
R79 = R: ASSEMBLY: SMD; AUTHOR: t5459927; BARCODE: 0100000001974; CATEGORY: Resistors; COMP: Resistor_R79; COMPONENTNAME: Resistor_R79_Resistor_R79; COMPONENTTYPE: 4; DATASHEET URL: http://www.yageo.com/NewPortal/yageodocoutput?fileName; DATE: 2024/2/16; FAMILY: RESISTOR; ID: 228; INSTANCENAME: INS6393; ITEM_ID: 462; MANUFACTURER: Yageo; MANUFACTURER PART NUMBER: RC0805FR-0710KL; NOTMOUNT: NOT MOUNT; NUMBER DEVICES IN PACKAGE: 1; PACKAGE CASE: 0805 (2012 Metric); PART TYPE: Resistors; PIN NAMES ROTATE: True; PIN NAMES VISIBLE: False; PIN NUMBERS VISIBLE: False; POWER: 0.125W, 1/8W; RECOMMENDED RATING: Platinum; SAVECOUNT: 0; SIZECODESMD: 2012; TEMPERATURE COEFFICIENT: }100ppm/C; TIME: 16:56:38; TOLERANCE: }1%; UPDATEDATE: 2024/2/16; UPDATETIME: 16:56:38; UPDATEUSER: t5459927
R80 = R: ASSEMBLY: SMD; AUTHOR: t5459927; BARCODE: 0100000001974; CATEGORY: Resistors; COMP: Resistor_R80; COMPONENTNAME: Resistor_R80_Resistor_R80; COMPONENTTYPE: 4; DATASHEET URL: http://www.yageo.com/NewPortal/yageodocoutput?fileName; DATE: 2024/2/16; FAMILY: RESISTOR; ID: 228; INSTANCENAME: INS6383; ITEM_ID: 462; MANUFACTURER: Yageo; MANUFACTURER PART NUMBER: RC0805FR-0710KL; NOTMOUNT: NOT MOUNT; NUMBER DEVICES IN PACKAGE: 1; PACKAGE CASE: 0805 (2012 Metric); PART TYPE: Resistors; PIN NAMES ROTATE: True; PIN NAMES VISIBLE: False; PIN NUMBERS VISIBLE: False; POWER: 0.125W, 1/8W; RECOMMENDED RATING: Platinum; SAVECOUNT: 0; SIZECODESMD: 2012; TEMPERATURE COEFFICIENT: }100ppm/C; TIME: 16:56:48; TOLERANCE: }1%; UPDATEDATE: 2024/2/16; UPDATETIME: 16:56:48; UPDATEUSER: t5459927
R89 = R: ASSEMBLY: SMD; AUTHOR: t5459927; BARCODE: 2911010041359; CATEGORY: Resistors; COMP: Resistor_R89; COMPONENTNAME: Resistor_R89_Resistor_R89; COMPONENTTYPE: 4; DATASHEET URL: http://www.yageo.com/NewPortal/yageodocoutput?fileName; DATE: 2024/2/16; FAMILY: RESISTOR; ID: 51; INSTANCENAME: INS6367; ITEM_ID: 4815; MANUFACTURER: Yageo; MANUFACTURER PART NUMBER: RC0402FR-0747RL; NUMBER DEVICES IN PACKAGE: 1; PACKAGE CASE: 0402 (1005 Metric); PART TYPE: Resistors; PIN NAMES ROTATE: True; PIN NAMES VISIBLE: False; PIN NUMBERS VISIBLE: False; POWER: 0.063W, 1/16W; SAVECOUNT: 0; SIZECODESMD: 1005; TEMPERATURE COEFFICIENT: }100ppm/C; TIME: 16:56:49; TOLERANCE: }1%; UPDATEDATE: 2024/2/16; UPDATETIME: 16:56:49; UPDATEUSER: t5459927; VAL1: 47(F); VAL2: 63mW; VAL3: RC0402FR-0747RL
RT1 = THM: ASSEMBLY: SMD; BARCODE: 0100000108543; CATEGORY: Sensors, Transducers; COMP: Resistor_NTC_RT1; COMPONENTNAME: Resistor_NTC_RT1_Resistor_NTC_RT1; COMPONENTTYPE: 4; DATASHEET URL: http://www.murata.com/~/media/webrenewal/support/library/catalog/products/thermistor/ntc/r44e.ashx; FAMILY: THERMISTOR NTC; ID: 388; INSTANCENAME: INS5165; ITEM_ID: 9968; MANUFACTURER: Murata Electronics North America; MANUFACTURER PART NUMBER: NCP18XH103F03RB; NUMBER DEVICES IN PACKAGE: 1; PACKAGE CASE: 0603 (1608 Metric); PART TYPE: Resistors; PIN NAMES ROTATE: True; PIN NAMES VISIBLE: False; PIN NUMBERS VISIBLE: False; RESISTANCE IN OHMS 25C: 10k; RESISTANCE TOLERANCE: }1%; SIZECODESMD: 1608; VAL1: 10K; VAL3: NCP18XH103F03RB
U?#1 = WAKU_DEF100: AUTHOR: w20165dm; COMPONENTTYPE: 2; DATE: 2024/03/12; DRAWINGNUMBER: RD228-SCHEMATIC-01; FUNCTION: Onboard Inverter; LAYOUTNAME: Z-29bafe88-5e4d-49ea-814c-92cf843dcf65.cmp51; REVISION: 01; SAVEAREA0: 185750,-43960,448537,75779; SAVECOUNT: 9; SHEETNUMBER: 6/7; SHTSAVECOUNT: 57; TIME: 13:12:26; TITLE: Motor Driving Circuit for Automotive / Body Using SmartMCD (TM); UPDATEDATE: 2024/03/26; UPDATETIME: 12:24:26

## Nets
GND: C42.2(1) J5.35 J5.37 J5.39 R63.1 RT1.2 ; also on sheet 1 3 4 5 6 7
VBAT: C42.1(2) J5.1 J5.3 J5.5 ; also on sheet 1 7
VBAT_INT: J5.2 J5.4 J5.6 Q2.1 Q2.2 Q2.5 Q2.6 Q3.1 Q3.2 Q3.5 Q3.6 Q4.1 Q4.2 Q4.5 Q4.6
COM: J5.33 ; also on sheet 7
COM_INT: J5.34 R78.1
G_HS_U: J5.26 R27.1
G_HS_V: J5.20 R28.1
G_HS_W: J5.14 R29.1
G_LS_U: J5.22 R37.1
G_LS_V: J5.16 R38.1
G_LS_W: J5.10 R39.1
GHU: J5.25 ; also on sheet 7
GHV: J5.19 ; also on sheet 7
GHW: J5.13 ; also on sheet 7
GLU: J5.21 ; also on sheet 7
GLV: J5.15 ; also on sheet 7
GLW: J5.9 ; also on sheet 7
LS_SOURCE: J5.30 Q5.4 Q6.4 Q7.4 R40.1 R41.1 R42.1 R43.2 R89.1
M_U: J5.24 R70.1
M_V: J5.18 R71.1
M_W: J5.12 R72.1
PHASE_U: CN1.1 DZ4.2 Q2.4 Q5.1 Q5.2 Q5.5 Q5.6 R30.1 R70.2 R80.1
PHASE_V: CN1.2 DZ5.2 Q3.4 Q6.1 Q6.2 Q6.5 Q6.6 R31.1 R71.2 R79.1
PHASE_W: CN1.3 DZ6.2 Q4.4 Q7.1 Q7.2 Q7.5 Q7.6 R32.1 R72.2 R77.1
RSH: J5.29 ; also on sheet 3 7
RSL: J5.31 ; also on sheet 3 7
RSL_INT: J5.32 J5.36 J5.38 J5.40 R43.1
SIG41: DZ1.1 DZ4.1
SIG42: DZ1.2 Q2.3 R27.2 R30.2
SIG43: DZ2.1 DZ5.1
SIG44: R77.2 R78.2 R79.2 R80.2
SIG45: J5.8 RT1.1
SIG46: Q5.3 R37.2 R40.2
SIG47: Q6.3 R38.2 R41.2
SIG48: DZ2.2 Q3.3 R28.2 R31.2
SIG49: DZ3.1 DZ6.1
SIG50: DZ3.2 Q4.3 R29.2 R32.2
SIG51: Q7.3 R39.2 R42.2
SLC: J5.27 ; also on sheet 7
SLC_INT: J5.28 R89.2
TEMP: J5.7 R63.2 ; also on sheet 6
U: J5.23 ; also on sheet 7
V: J5.17 ; also on sheet 7
W: J5.11 ; also on sheet 7

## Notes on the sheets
sheet 2
- *1
- RSH_INT
- RSL_INT
- *1 Kelvin connection from R43 to J5
- *2
- RSH_INT
- KELVIN SENSE
- RSL_INT
- *2 Kelvin Connection from R43 to J5
